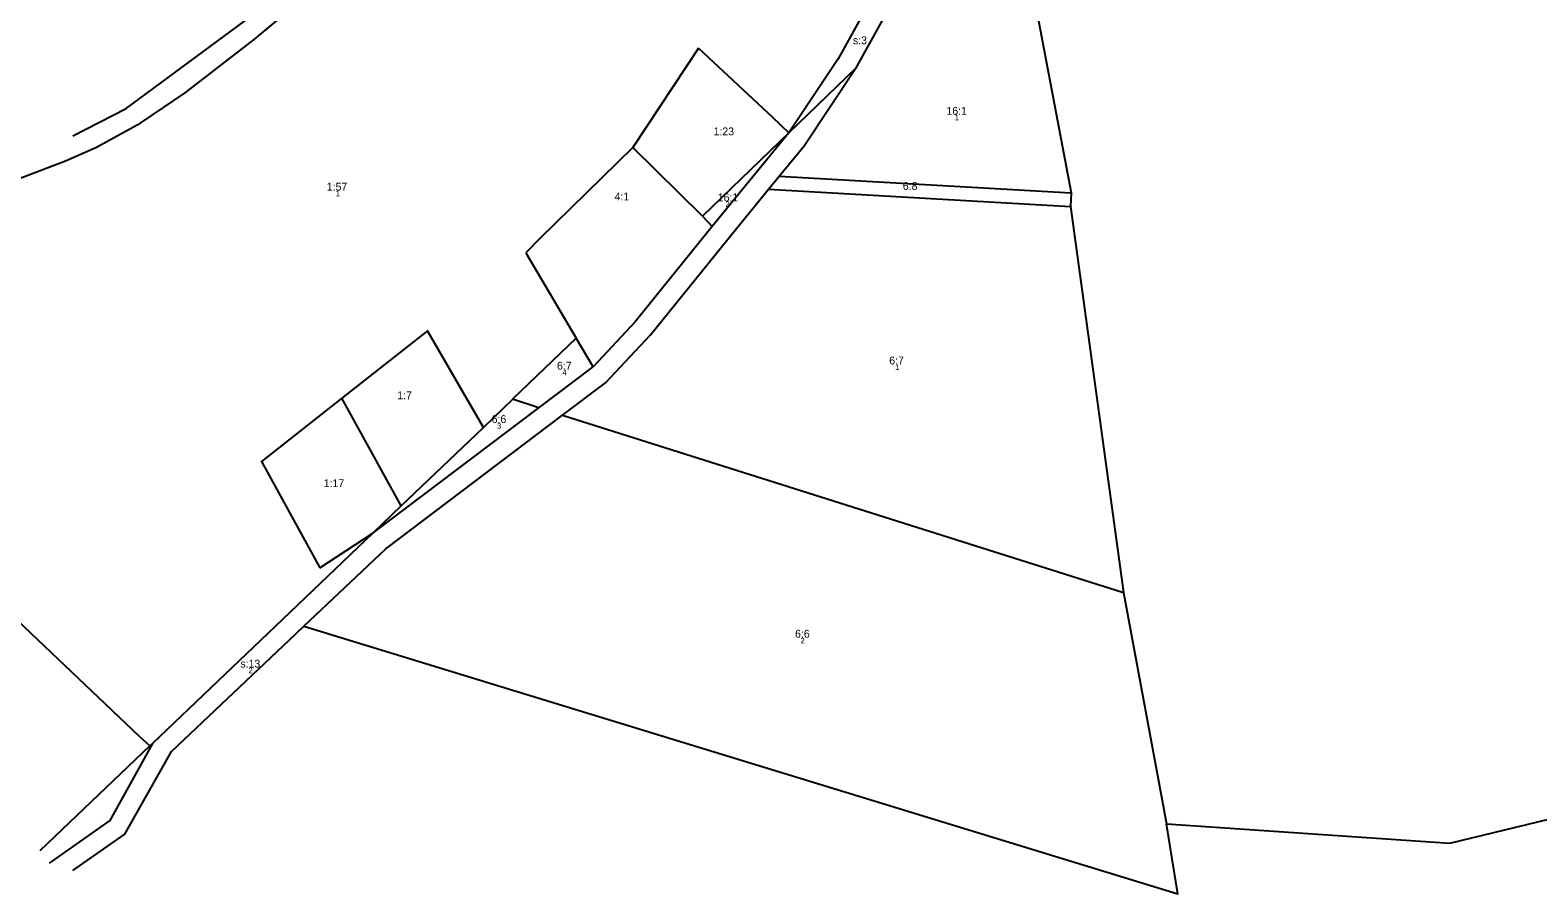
# Model space of a CAD drawing. Extents: x 140824 to 143748, y 6547319 to 6550906.
# Drawn here: x 141165 to 141835, y 6547619 to 6548002 of the extents above; entities that cross this region are included whole.
import ezdxf

# ---------------------------------------------------------------- set-up
doc = ezdxf.new("R2010")
doc.units = 0
for name, color, linetype in [('FAST Fastighetsgräns', 7, 'Continuous'), ('FAST Områdesnummer för fastighet', 7, 'Continuous'), ('FAST Områdesnummer för samfällighet', 7, 'Continuous'), ('FAST Registernummer för fastighet', 7, 'Continuous'), ('FAST Registernummer för samfällighet', 7, 'Continuous'), ('FAST Traktgräns', 7, 'Continuous')]:
    doc.layers.add(name, color=color, linetype=linetype)

msp = doc.modelspace()

# ---------------------------------------------------------------- linework, layer by layer
at = {"layer": 'FAST Fastighetsgräns'}
for p, q in [((141462.07, 6547994.11), (141432.93, 6547950.1)), ((141502.21, 6547956.52), (141468.19, 6547915.05)), ((141463.87, 6547919.52), (141432.93, 6547950.1)), ((141493.23, 6547931.52), (141497.94, 6547937.26)), ((141497.94, 6547937.26), (141627.57, 6547929.89)), ((141493.23, 6547931.52), (141627.23, 6547923.9)), ((141385.48, 6547903.37), (141407.84, 6547865.47)), ((141391.32, 6547834.5), (141415.35, 6547852.75)), ((141330.15, 6547790.99), (141303.82, 6547838.76)), ((141391.32, 6547834.5), (141379.62, 6547838.3)), ((141317.5, 6547778.78), (141391.32, 6547834.5)), ((141401.75, 6547831.21), (141650.77, 6547752.44)), ((141293.96, 6547763.48), (141317.5, 6547778.78))]:
    msp.add_line(p, q, dxfattribs=at)
for points in [[(140980.52, 6547910.3), (140990.98, 6547909.95), (141033.02, 6547907.12), (141056.85, 6547907.1), (141074.94, 6547908.7), (141090.36, 6547911.46), (141112.78, 6547918.14), (141181.19, 6547944.15), (141194.83, 6547950.24), (141214.56, 6547960.98), (141234.26, 6547974.33), (141264.91, 6547997.93), (141285.93, 6548015.65), (141321.46, 6548046.93), (141413.91, 6548119.44), (141453.09, 6548145.51), (141468.41, 6548156.81), (141488.02, 6548173.66), (141505.13, 6548189.58), (141522.91, 6548203.37), (141542.31, 6548215.28), (141586.97, 6548234.3)], [(141184.36, 6547955.19), (141208.02, 6547967.36), (141261.24, 6548006.65), (141296.63, 6548036.78)], [(141544.82, 6548027.04), (141524.07, 6547989.44), (141502.21, 6547956.52)], [(141462.07, 6547994.11), (141494.9, 6547963.49), (141502.21, 6547956.52)], [(141497.94, 6547937.26), (141509.1, 6547950.87), (141531.87, 6547985.14)], [(141432.93, 6547950.1), (141391.65, 6547909.71), (141385.48, 6547903.37)], [(141401.75, 6547831.21), (141420.78, 6547845.57), (141440.77, 6547866.86), (141475.08, 6547909.4), (141493.23, 6547931.52)], [(140980.52, 6547910.3), (140981.9, 6547909.07), (141213.87, 6547688.8), (141218.54, 6547684.38)], [(141366.63, 6547825.79), (141341.76, 6547868.66), (141303.82, 6547838.76)], [(141303.82, 6547838.76), (141268.11, 6547810.62), (141293.96, 6547763.48)], [(141287, 6547737.59), (141323.27, 6547771.97), (141401.75, 6547831.21)], [(141184.39, 6547629.16), (141207.49, 6547645.21), (141228.25, 6547681.89), (141283.34, 6547734.12), (141287, 6547737.59)], [(141287, 6547737.59), (141674.9, 6547618.74), (141669.8, 6547649.89)], [(141219.73, 6547685.52), (141200.74, 6547651.37), (141173.82, 6547632.39)]]:
    msp.add_lwpolyline(points, dxfattribs=at)
at = {"layer": 'FAST Traktgräns'}
for p, q in [((141603.86, 6548054.53), (141627.57, 6547929.89)), ((141531.87, 6547985.14), (141502.21, 6547956.52)), ((141502.21, 6547956.52), (141463.87, 6547919.52)), ((141627.57, 6547929.89), (141627.23, 6547923.9)), ((141627.23, 6547923.9), (141650.77, 6547752.44)), ((141463.87, 6547919.52), (141468.19, 6547915.05)), ((141407.84, 6547865.47), (141379.62, 6547838.3)), ((141415.35, 6547852.75), (141407.84, 6547865.47)), ((141379.55, 6547838.23), (141366.63, 6547825.79)), ((141379.62, 6547838.3), (141379.55, 6547838.23)), ((141330.15, 6547790.99), (141366.63, 6547825.79)), ((141330.15, 6547790.99), (141317.5, 6547778.78)), ((141317.5, 6547778.78), (141277.4, 6547740.53)), ((141650.77, 6547752.44), (141669.8, 6547649.89)), ((141277.4, 6547740.53), (141219.73, 6547685.52)), ((141218.54, 6547684.38), (141169.78, 6547637.86)), ((141219.73, 6547685.52), (141218.54, 6547684.38))]:
    msp.add_line(p, q, dxfattribs=at)
for points in [[(141601.6, 6548079.32), (141593.5, 6548066.61), (141564.93, 6548038.08), (141552.23, 6548022.07), (141531.87, 6547985.14)], [(141468.19, 6547915.05), (141434.03, 6547872.7), (141415.35, 6547852.75)], [(141669.8, 6547649.89), (141795.57, 6547641.3), (142043.35, 6547701.25)]]:
    msp.add_lwpolyline(points, dxfattribs=at)

# ---------------------------------------------------------------- texts
at = {"layer": 'FAST Områdesnummer för fastighet'}
for s, p in [('1', (141575.85, 6547962.07)), ('1', (141301.09, 6547928.43)), ('2', (141474.11, 6547923.64)), ('4', (141401.71, 6547848.94)), ('1', (141549.42, 6547851.24)), ('3', (141372.7, 6547825.24)), ('2', (141507.39, 6547729.94))]:
    msp.add_text(s, height=2.5, dxfattribs=at).set_placement(p)
at = {"layer": 'FAST Områdesnummer för samfällighet'}
msp.add_text('2', height=2.5, dxfattribs=at).set_placement((141262.38, 6547716.67))
at = {"layer": 'FAST Registernummer för fastighet'}
for s, p in [('16:1', (141572.2, 6547964.57)), ('1:23', (141468.8, 6547955.45)), ('1:57', (141297.09, 6547930.93)), ('4:1', (141424.87, 6547926.57)), ('16:1', (141470.68, 6547926.14)), ('6:8', (141552.83, 6547931.22)), ('6:7', (141546.78, 6547853.74)), ('6:7', (141399.31, 6547851.44)), ('1:7', (141328.39, 6547838.28)), ('6:6', (141370.3, 6547827.74)), ('1:17', (141295.74, 6547799.29)), ('6:6', (141504.98, 6547732.44))]:
    msp.add_text(s, height=3.5, dxfattribs=at).set_placement(p)
at = {"layer": 'FAST Registernummer för samfällighet'}
for s, p in [('s:3', (141530.67, 6547995.9)), ('s:13', (141258.75, 6547719.17))]:
    msp.add_text(s, height=3.5, dxfattribs=at).set_placement(p)

doc.saveas('drawing.dxf')
